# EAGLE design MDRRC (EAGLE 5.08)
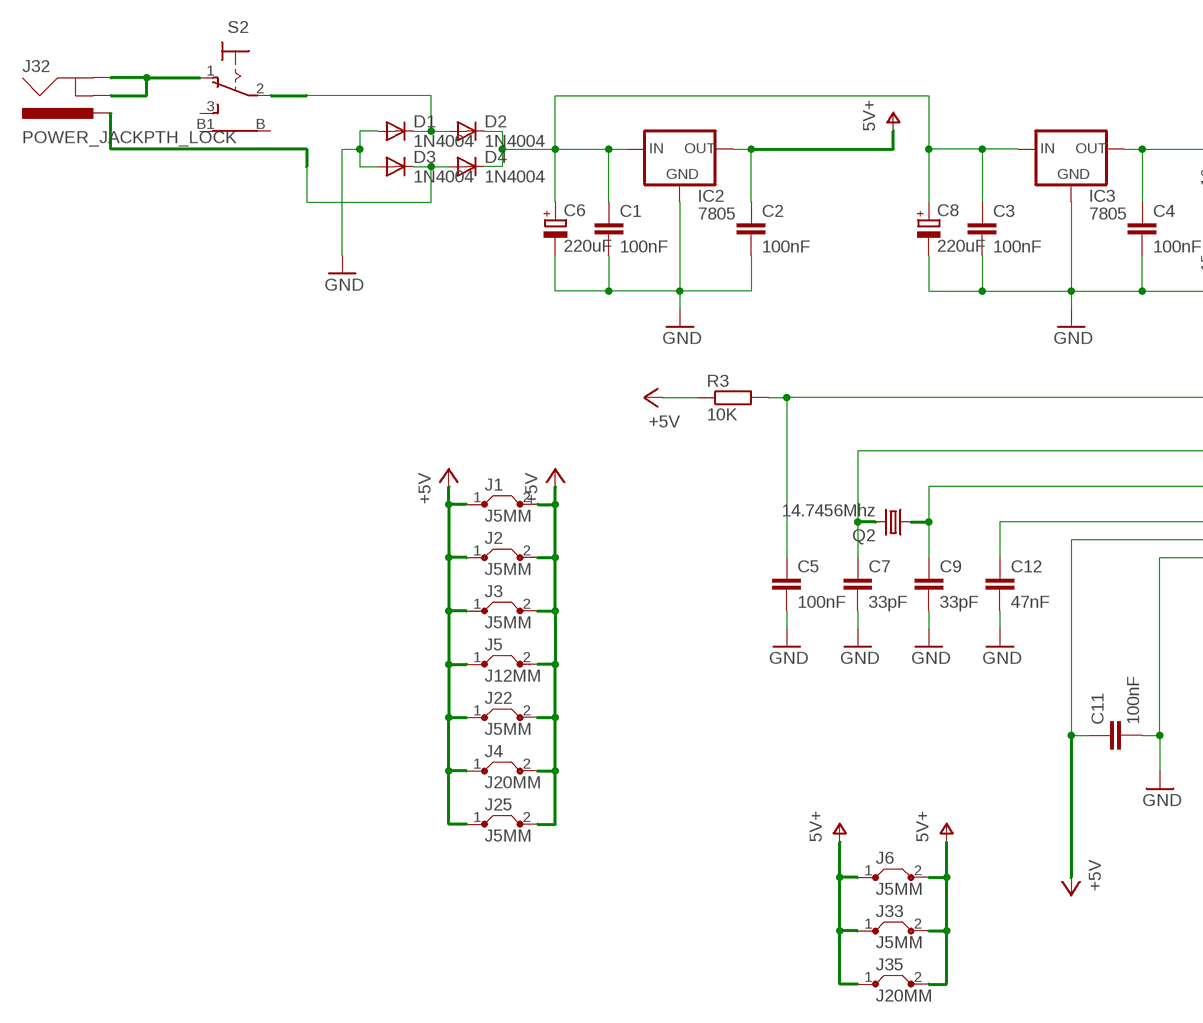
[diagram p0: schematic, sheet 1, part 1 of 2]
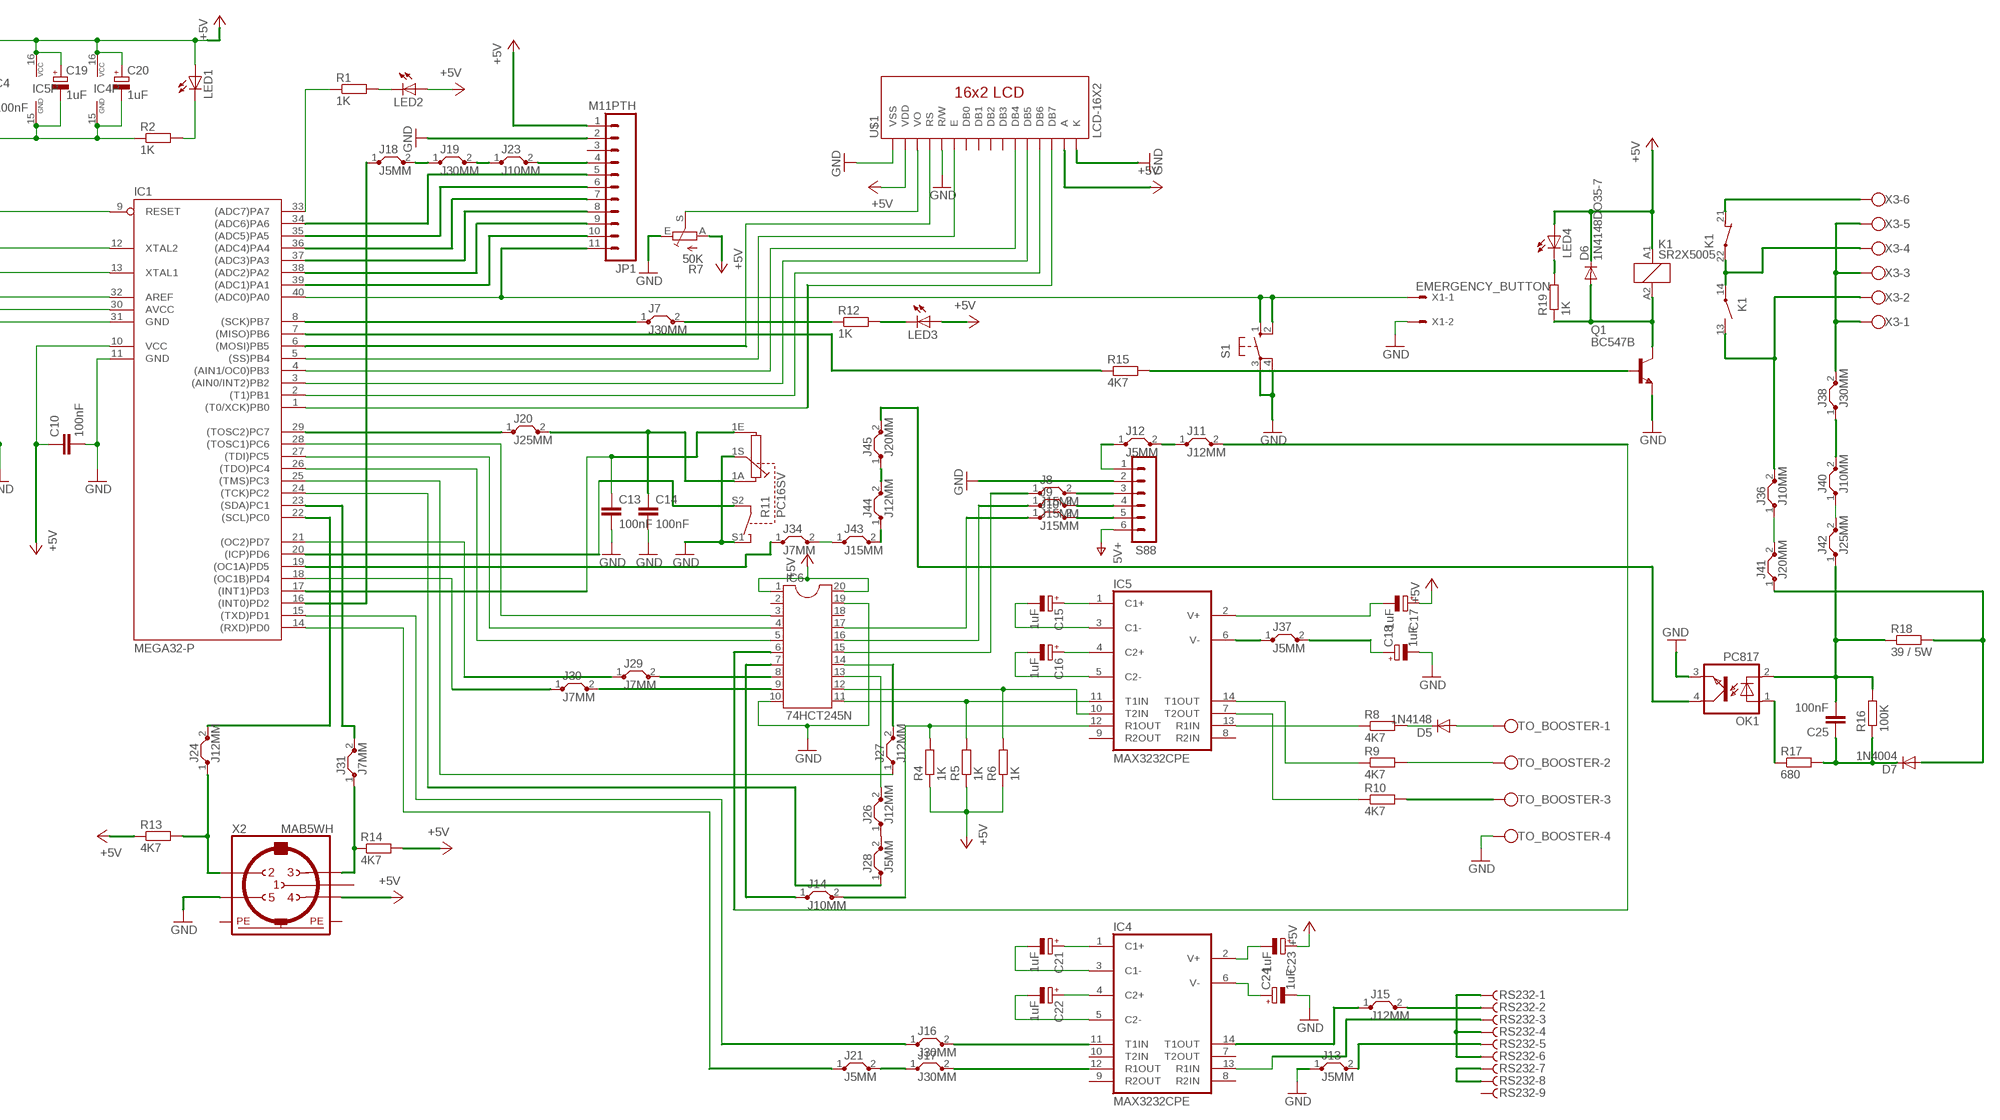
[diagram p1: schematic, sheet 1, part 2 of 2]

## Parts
C1  100nF  C-EU025-025X050  [C025-025X050]
C2  100nF  C-EU025-025X050  [C025-025X050]
C3  100nF  C-EU025-025X050  [C025-025X050]
C4  100nF  C-EU025-025X050  [C025-025X050]
C5  100nF  C-EU025-025X050  [C025-025X050]
C6  220uF  CPOL-EUE2.5-5  [E2,5-5]
C7  33pF  C-EU025-025X050  [C025-025X050]
C8  220uF  CPOL-EUE2.5-5  [E2,5-5]
C9  33pF  C-EU025-025X050  [C025-025X050]
C10  100nF  C-EU025-025X050  [C025-025X050]
C11  100nF  C-EU025-025X050  [C025-025X050]
C12  47nF  C-EU025-025X050  [C025-025X050]
C13  100nF  C-EU025-025X050  [C025-025X050]
C14  100nF  C-EU025-025X050  [C025-025X050]
C15  1uF  CPOL-EUE1.8-4  [E1,8-4]
C16  1uF  CPOL-EUE1.8-4  [E1,8-4]
C17  1uF  CPOL-EUE1.8-4  [E1,8-4]
C18  1uF  CPOL-EUE1.8-4  [E1,8-4]
C19  1uF  CPOL-EUE1.8-4  [E1,8-4]
C20  1uF  CPOL-EUE1.8-4  [E1,8-4]
C21  1uF  CPOL-EUE1.8-4  [E1,8-4]
C22  1uF  CPOL-EUE1.8-4  [E1,8-4]
C23  1uF  CPOL-EUE1.8-4  [E1,8-4]
C24  1uF  CPOL-EUE1.8-4  [E1,8-4]
C25  100nF  C-EU025-025X050  [C025-025X050]
D1  1N4004  [DO41-10]
D2  1N4004  [DO41-10]
D3  1N4004  [DO41-10]
D4  1N4004  [DO41-10]
D5  1N4148  1N4148DO35-10  [DO35-10]
D6  1N4148DO35-7  [DO35-7]
D7  1N4004  [DO41-10]
IC1  MEGA32-P  [DIL40]
IC2  7805  78XXS  [78XXS]
IC3  7805  78XXS  [78XXS]
IC4  MAX3232CPE  [DIL16]
IC5  MAX3232CPE  [DIL16]
IC6  74HCT245N  DIL20  [DIL20]
J1  J5MM  [05]
J2  J5MM  [05]
J3  J5MM  [05]
J4  J20MM  [20]
J5  J12MM  [12]
J6  J5MM  [05]
J7  J30MM  [30]
J8  J15MM  [15]
J9  J15MM  [15]
J10  J15MM  [15]
J11  J12MM  [12]
J12  J5MM  [05]
J13  J5MM  [05]
J14  J10MM  [10]
J15  J12MM  [12]
J16  J30MM  [30]
J17  J30MM  [30]
J18  J5MM  [05]
J19  J30MM  [30]
J20  J25MM  [25]
J21  J5MM  [05]
J22  J5MM  [05]
J23  J10MM  [10]
J24  J12MM  [12]
J25  J5MM  [05]
J26  J12MM  [12]
J27  J12MM  [12]
J28  J5MM  [05]
J29  J7MM  [07]
J30  J7MM  [07]
J31  J7MM  [07]
J32  POWER_JACKPTH_LOCK  [POWER_JACK_PTH_LOCK]
J33  J5MM  [05]
J34  J7MM  [07]
J35  J20MM  [20]
J36  J10MM  [10]
J37  J5MM  [05]
J38  J30MM  [30]
J40  J10MM  [10]
J41  J20MM  [20]
J42  J25MM  [25]
J43  J15MM  [15]
J44  J12MM  [12]
J45  J20MM  [20]
JP1  M11PTH  [1X11]
K1  SR2X5005  [SR2X]
LED1  LED3MM  [LED3MM]
LED2  LED3MM  [LED3MM]
LED3  LED3MM  [LED3MM]
LED4  LED3MM  [LED3MM]
OK1  PC817  [DIL04]
Q1  BC547B  [TO92]
Q2  14.7456Mhz  CRYSTALHC18U-H  [HC18U-H]
R1  1K  R-EU_0207/10  [0207/10]
R2  1K  R-EU_0207/10  [0207/10]
R3  10K  R-EU_0207/10  [0207/10]
R4  1K  R-EU_0207/10  [0207/10]
R5  1K  R-EU_0207/10  [0207/10]
R6  1K  R-EU_0207/10  [0207/10]
R7  50K  TRIM_EU-CA6V  [CA6V]
R8  4K7  R-EU_0207/10  [0207/10]
R9  4K7  R-EU_0207/10  [0207/10]
R10  4K7  R-EU_0207/10  [0207/10]
R11  PC16SV  [PC16SV]
R12  1K  R-EU_0207/10  [0207/10]
R13  4K7  R-EU_0207/10  [0207/10]
R14  4K7  R-EU_0207/10  [0207/10]
R15  4K7  R-EU_0207/10  [0207/10]
R16  100K  R-EU_0207/10  [0207/10]
R17  680  R-EU_0207/10  [0207/10]
R18  39 / 5W  R-EU_V235/17  [V235/17]
R19  1K  R-EU_0207/10  [0207/10]
RS232  F09HPS  [F09HP]
S1  10-XX  [B3F-10XX]
S2  LPV-1  [LPV-1]
S88  MA06-1  [MA06-1]
TO_BOOSTER  W237-04P  [W237-4P]
U$1  LCD-16X2  [LCD-16X2]
X1  EMERGENCY_BUTTON  22-23-2021  [22-23-2021]
X2  MAB5WH  [MAB5WH]
X3  W237-06P  [W237-6P]

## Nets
+5V: C4.1 C10.1 C11.1 C17.+ C19.+ C20.+ C23.+ D6.C IC1.10(VCC) IC1.30(AVCC) IC3.OUT IC4.16(VCC) IC5.16(VCC) IC6.1 IC6.20 J1.1 J1.2 J2.1 J2.2 J3.1 J3.2 J4.1 J4.2 J5.1 J5.2 J22.1 J22.2 J25.1 J25.2 JP1.1 K1.A1 LED1.A LED2.A LED3.A LED4.A R3.1 R4.1 R5.1 R6.1 R7.A R13.1 R14.2 U$1.2(VDD) U$1.15(A) X2.4
GND: C1.2 C2.2 C3.2 C4.2 C5.2 C6.- C7.2 C8.- C9.2 C10.2 C11.2 C12.2 C13.2 C14.2 C18.- C19.- C20.- C24.- D1.A D3.A IC1.11(GND) IC1.31(GND) IC2.GND IC3.GND IC4.15(GND) IC5.15(GND) IC6.10 IC6.19 J13.1 JP1.2 OK1.3(EMIT) Q1.1(E) R2.1 R7.E R11.1S R11.S1 S1.3(P) S1.4(P1) S88.2 TO_BOOSTER.4 U$1.1(VSS) U$1.5(R/W) U$1.16(K) X1.2 X2.5
N$1: D1.C D2.A S2.2(P)
N$2: D3.C D4.A J32.PWR
N$3: C7.1 IC1.12(XTAL2) Q2.2
N$4: C1.1 C3.1 C6.+ C8.+ D2.C D4.C IC2.IN IC3.IN
N$5: C9.1 IC1.13(XTAL1) Q2.1
N$6: C12.1 IC1.32(AREF)
N$7: LED1.K(C) R2.2
N$8: C5.1 IC1.9(RESET) R3.2
N$9: IC1.33((ADC7)PA7) R1.1
N$10: LED2.K(C) R1.2
N$11: IC1.40((ADC0)PA0) JP1.11 S1.1(S) S1.2(S1) X1.1
N$12: IC1.8((SCK)PB7) J7.1
N$13: LED3.K(C) R12.2
N$14: IC6.7 J14.1
N$15: IC1.28((TOSC1)PC6) IC6.3
N$16: IC1.27((TDI)PC5) IC6.4
N$17: IC1.26((TDO)PC4) IC6.5
N$18: IC1.21((OC2)PD7) J29.1
N$19: IC1.18((OC1B)PD4) J30.1
N$20: IC1.25((TMS)PC3) J27.1
N$21: IC1.24((TCK)PC2) J28.1
N$22: C14.1 J20.2 R11.1A
N$23: IC5.11(T1IN) IC6.11 R5.2
N$24: IC5.10(T2IN) IC6.12 R6.2
N$25: IC5.12(R1OUT) J14.2 R4.2
N$26: J7.2 R12.1
N$27: C16.- IC5.5(C2-)
N$28: C15.- IC5.3(C1-)
N$29: C15.+ IC5.1(C1+)
N$30: C16.+ IC5.4(C2+)
N$31: C17.- IC5.2(V+)
N$32: C18.+ J37.2
N$33: IC6.6 J11.2
N$34: IC6.15 J8.1
N$35: IC6.16 J9.1
N$36: IC6.17 J10.1
N$37: C21.+ IC4.1(C1+)
N$38: C21.- IC4.3(C1-)
N$39: C22.+ IC4.4(C2+)
N$40: C22.- IC4.5(C2-)
N$41: C23.- IC4.2(V+)
N$42: C24.+ IC4.6(V-)
N$43: IC1.15((TXD)PD1) J16.1
N$44: IC1.14((RXD)PD0) J21.1
N$45: IC4.14(T1OUT) J15.1
N$46: IC4.13(R1IN) RS232.3
N$47: IC1.1((T0/XCK)PB0) U$1.14(DB7)
N$48: IC1.2((T1)PB1) U$1.13(DB6)
N$49: IC1.3((AIN0/INT2)PB2) U$1.12(DB5)
N$50: IC1.4((AIN1/OC0)PB3) U$1.11(DB4)
N$51: IC1.5((SS)PB4) U$1.6(E)
N$52: IC1.6((MOSI)PB5) U$1.4(RS)
N$53: R7.S U$1.3(VO)
N$54: IC5.14(T1OUT) R9.1
N$55: IC5.7(T2OUT) R10.1
N$56: IC5.13(R1IN) R8.1
N$57: R10.2 TO_BOOSTER.3
N$58: R9.2 TO_BOOSTER.2
N$59: D5.C R8.2
N$60: D5.A TO_BOOSTER.1
N$61: J8.2 S88.3
N$62: J9.2 S88.4
N$63: J10.2 S88.5
N$64: J12.1 S88.1
N$65: J11.1 J12.2
N$66: J13.2 RS232.5
N$67: IC1.7((MISO)PB6) R15.1
N$68: RS232.1 RS232.4 RS232.6
N$69: RS232.7 RS232.8
N$70: J15.2 RS232.2
N$71: IC4.11(T1IN) J16.2
N$72: IC1.39((ADC1)PA1) JP1.10
N$73: IC1.38((ADC2)PA2) JP1.9
N$74: IC4.12(R1OUT) J17.2
N$75: IC1.37((ADC3)PA3) JP1.8
N$76: J17.1 J21.2
N$77: IC6.13 J26.2
N$78: IC6.14 J27.2
N$79: J26.1 J28.2
N$80: IC6.8 J29.2
N$81: IC6.9 J30.2
N$82: IC1.22((SCL)PC0) J24.2
N$83: J32.GND J32.GNDBREAK S2.1(O)
N$84: IC1.20((ICP)PD6) R11.S2
N$85: C13.1 IC1.17((INT1)PD3) R11.1E
N$86: IC1.29((TOSC2)PC7) J20.1
N$87: IC1.36((ADC4)PA4) JP1.7
N$88: IC1.19((OC1A)PD5) J34.1
N$89: J36.1 J41.2
N$90: J34.2 J43.1
N$91: IC1.35((ADC5)PA5) JP1.6
N$92: IC1.34((ADC6)PA6) JP1.5
N$93: IC1.16((INT0)PD2) J18.1
N$94: J18.2 J19.1
N$95: J19.2 J23.1
N$96: J23.2 JP1.4
N$97: IC1.23((SDA)PC1) J31.2
N$98: J31.1 R14.1 X2.3
N$99: J24.1 R13.2 X2.2
N$100: IC5.6(V-) J37.1
N$101: Q1.2(B) R15.2
N$102: D6.A K1.A2 Q1.3(C) R19.1
N$103: J36.2 K1.13(3:S) X3.2
N$104: J38.1 J40.2
N$105: K1.14(3:P) K1.22(2:P) X3.4
N$106: J38.2 X3.1 X3.3 X3.5
N$108: K1.21(2:O) X3.6
N$109: J40.1 J42.2
N$110: J43.2 J44.1
N$111: J44.2 J45.1
N$112: J45.2 OK1.4(COL)
N$113: C25.2 J42.1 OK1.2(C) R16.2 R18.1
N$114: OK1.1(A) R17.1
N$115: C25.1 D7.C R16.1 R17.2
N$116: D7.A J41.1 R18.2
N$117: LED4.K(C) R19.2
V+: C2.1 IC2.OUT J6.1 J6.2 J33.1 J33.2 J35.1 J35.2 S88.6 ; supply symbol labelled 5V+
Unconnected: IC4.7(T2OUT) IC4.8(R2IN) IC4.9(R2OUT) IC4.10(T2IN) IC5.8(R2IN) IC5.9(R2OUT) IC6.2 IC6.18 JP1.3 RS232.9 S2.3(S) S2.B S2.B1 U$1.7(DB0) U$1.8(DB1) U$1.9(DB2) U$1.10(DB3) X2.1

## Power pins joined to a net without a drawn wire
PE: X2.PE X2.PE@(PE)

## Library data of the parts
C1-C5 C7 C9-C14 C25 = rcl:C-EU: CAPACITOR, European symbol
C6 C8 C15-C24 = rcl:CPOL-EU: POLARIZED CAPACITOR, European symbol
D1-D4 D7 = diode:1N4004: DIODE
D5 D6 = diode:1N4148: DIODE
IC1 = atmel:MEGA32-P: MICROCONTROLLER 32 Kbytes FLASH 2 Kbytes SRAM 1 Kbytes EEPROM USART 8-channel 10 bit ADC Source: www.atmel.com .. doc2503.pdf
IC2 IC3 = v-reg:78XXS: VOLTAGE REGULATOR
IC4 IC5 = maxim:MAX3232*: True RS-232 Transceivers 3.0V to 5.5V, Low-Power up to 1Mbps, Using Four 0.1µF External Capacitors Source: http://pdfserv.maxim-ic.com/en/ds/MAX3222-MAX3241.pdf
IC6 = ic-package:DIL20: Dual In Line / Socket
J1-J31 J33-J38 J40-J45 = jumper:J: Bridge
J32 = SparkFun:POWER_JACK: Power Jack This is the standard 5.5mm barrel jack for power. The PTH is the most common, proven, reliable, footprint. All others are experimental. The Slot footprint only works if the mill layer is transmitted to the PCB fab house so be warned. Spark Fun Electronics SKU : PRT-00119. Mating wall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
JP1 = SparkFun:M11: Header 11 Standard 11-pin 0.1" header. Use with straight break away headers (SKU : PRT-00116), right angle break away headers (PRT-00553), swiss pins (PRT-00743), machine pins (PRT-00117), and female headers (PRT-00115).
K1 = relay:SR2X5*: Safety Relay 2 pole 6 A SCHRACK Source: http://www.schrack.com/.. 5809.pdf
LED1-LED4 = led:LED: LED
OK1 = optocoupler:PC817: SHARP OPTO COUPLER
Q1 = transistor-npn:BC547*: NPN Transistor
Q2 = crystal:CRYSTAL: CRYSTAL
R1-R6 R8-R10 R12-R14 R16 R17 R19 = rcl:R-EU_: RESISTOR, European symbol
R7 = pot:TRIM_EU-: POTENTIOMETER
R11 = rotary_voti:PC16SV: POTENTIOMETER vertical single carbon potentiometer with switch, 16 mm
R15 R18 = resistor:R-EU_: RESISTOR, European symbol
RS232 = con-subd:F09?S: SUB-D
S1 = switch-omron:10-XX: OMRON SWITCH
S2 = switch:LPV-1: TOGGLE SWITCH
S88 = con-lstb:MA06-1: PIN HEADER
TO_BOOSTER = con-wago-508:W237-04P: WAGO SREW CLAMP
U$1 = SparkFun:LCD-16X2
X1 = con-molex:22-23-2021: .100" (2.54mm) Center Header - 2 Pin
X2 = con_midi:MAB5WH: Female CONNECTOR 5 pins with shield, horizontal (DIN 45327)
X3 = con-wago-508:W237-06P: WAGO SREW CLAMP

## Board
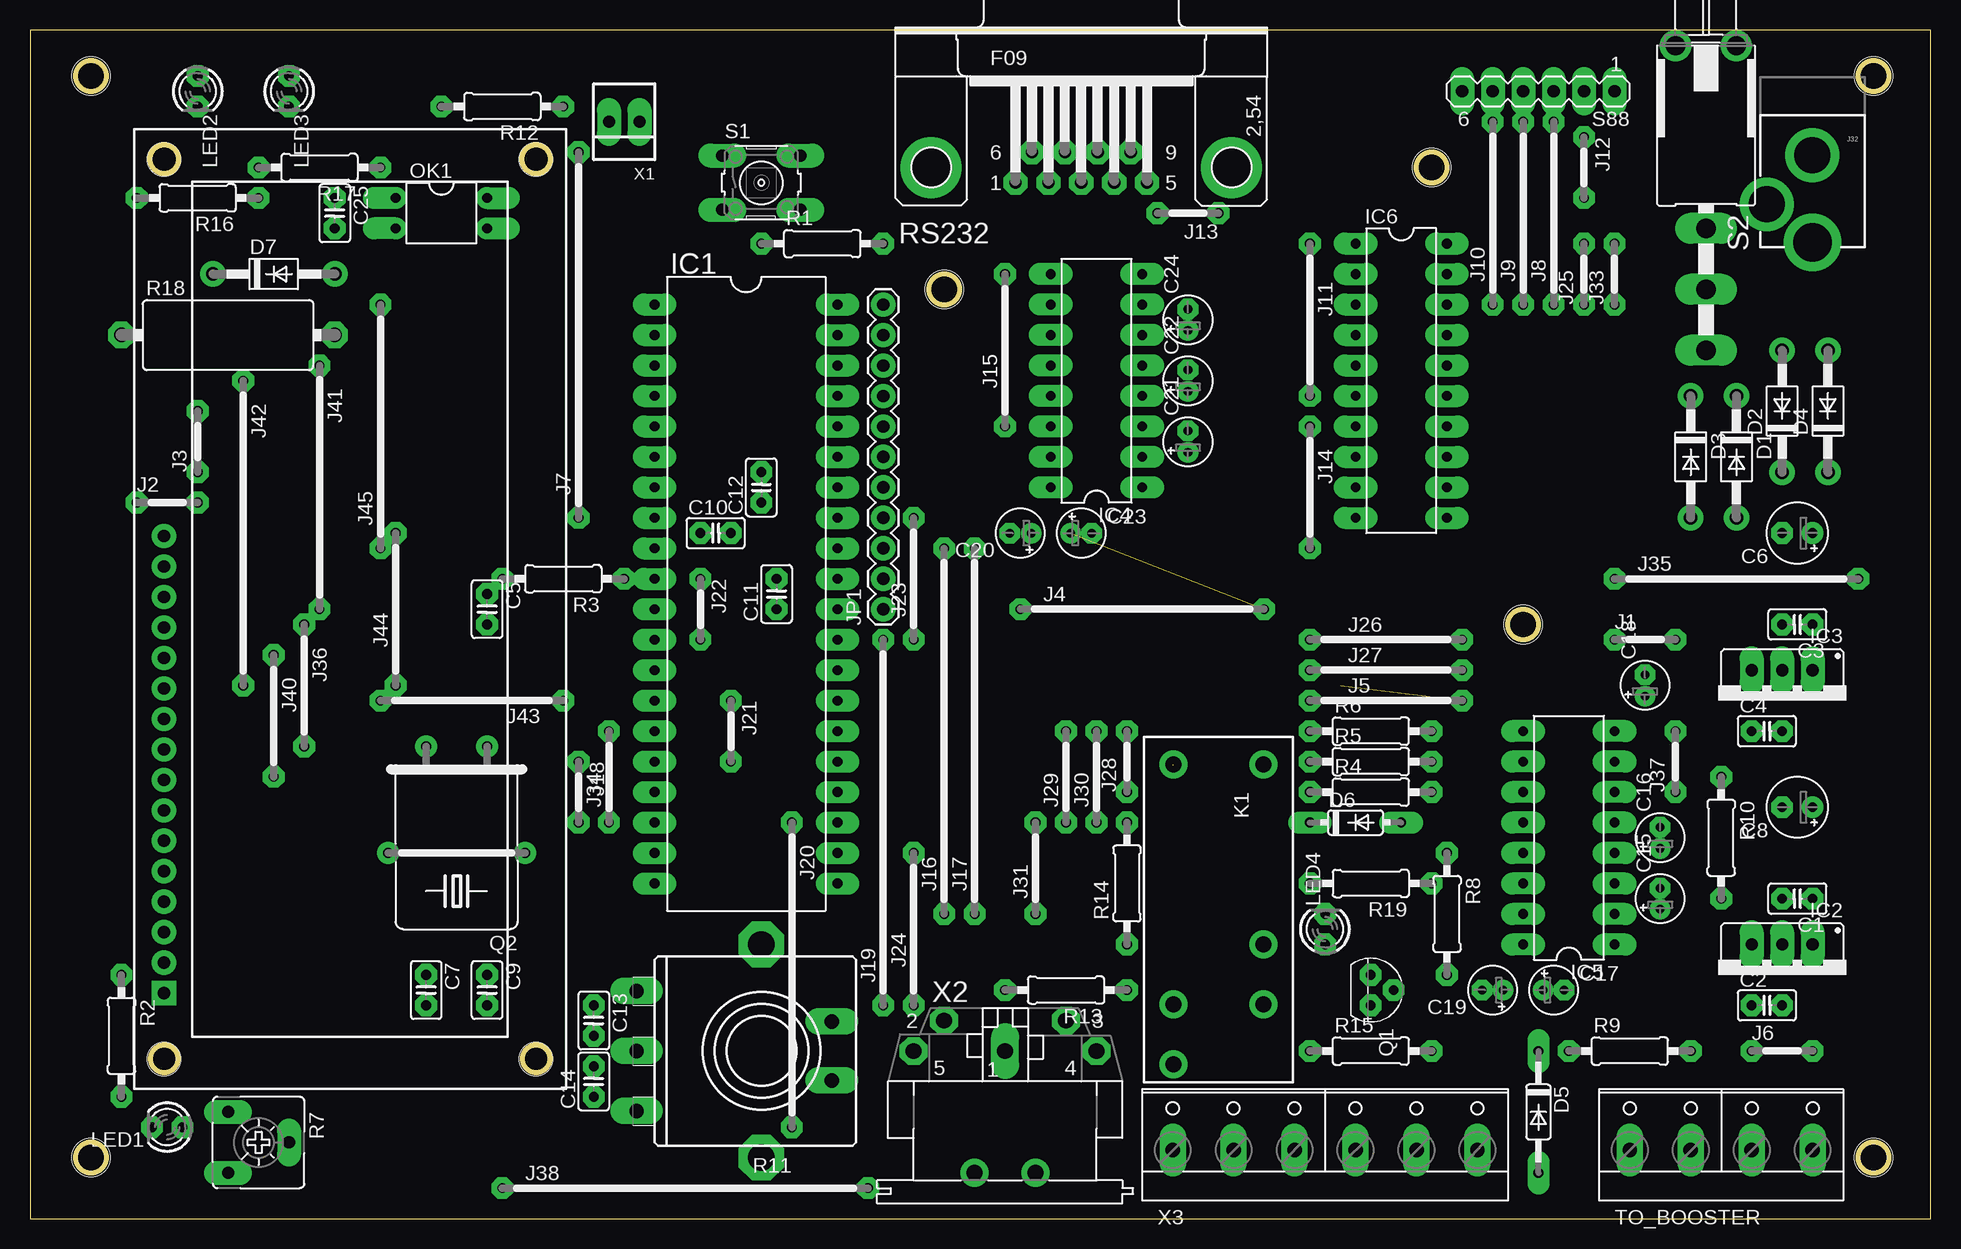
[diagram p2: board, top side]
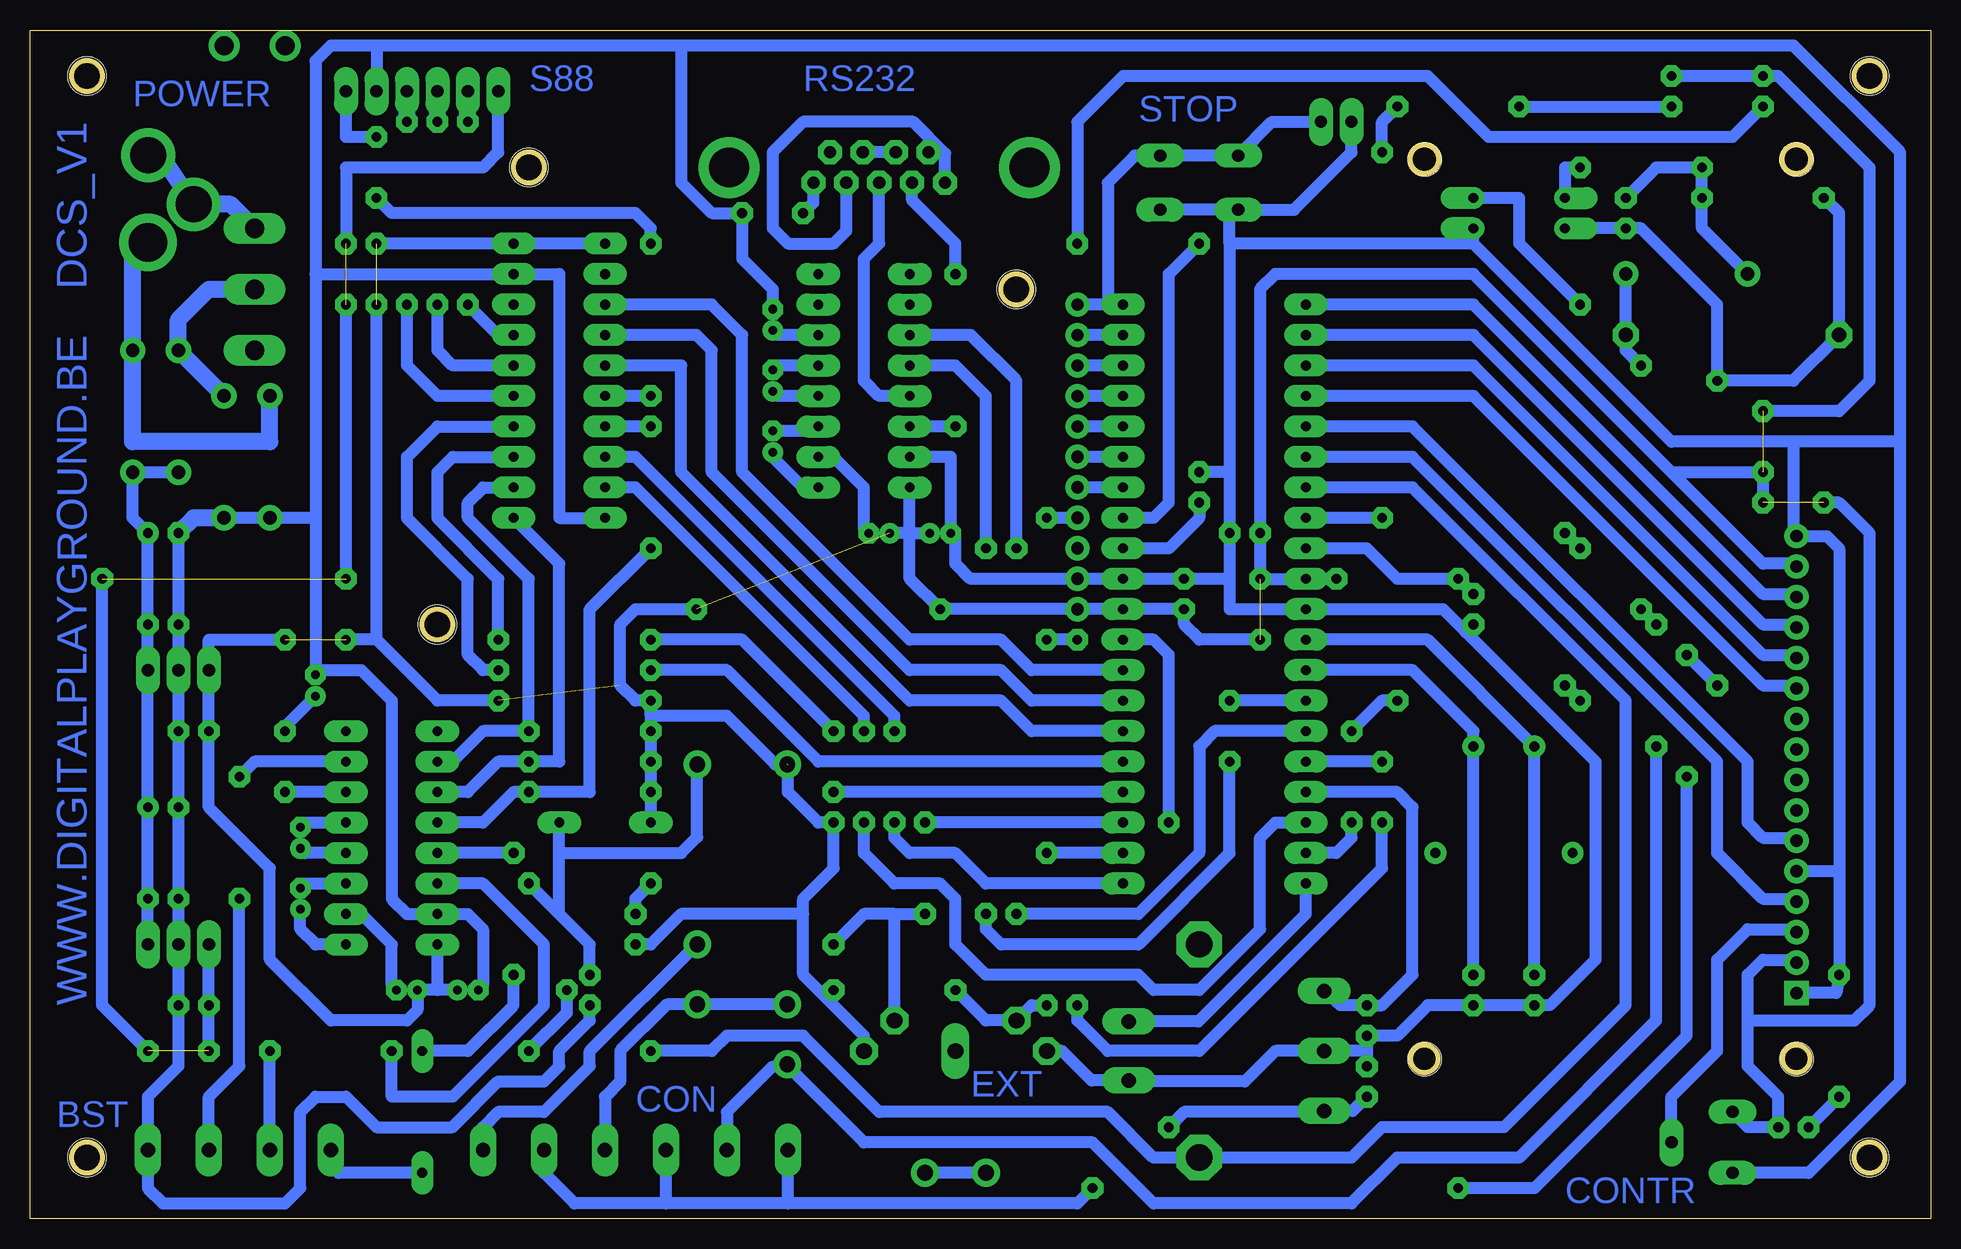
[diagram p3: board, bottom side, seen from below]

Size 158.42 x 99.05 mm. Coordinates in mm from the lower left corner, seen from the top.
Outline: 0,0 158.42,0 158.42,99.05 0,99.05 0,0
Outline: circle at 5.08,95.25 radius 1.27
Outline: circle at 5.08,5.08 radius 1.27
Outline: circle at 153.67,5.08 radius 1.27
Outline: circle at 153.67,95.25 radius 1.27
Outline: circle at 116.84,87.63 radius 1.27
Outline: circle at 76.2,77.47 radius 1.27
Outline: circle at 124.46,49.53 radius 1.27
Outline: circle at 42.2,13.33 radius 1.13
Outline: circle at 11.2,13.33 radius 1.13
Outline: circle at 11.2,88.33 radius 1.17
Outline: circle at 42.2,88.33 radius 1.17
Copper layers (1*16): Top 0.8mm / dielectric 1.3mm / Bottom 0.8mm
Design rules "DRC settings smallest": minimum track width 0.8mm, minimum drill 24mil, track to track 0.2mm, track to pad 0.2mm, pad to pad 0.2mm, via to via 0.2mm, smd to smd 8mil, copper to edge 0.3mm, drill to drill 0.3mm, minimum pad ring 0.5mm, minimum via ring 1mm, stop-mask expansion 4mil, vias tented up to drill 0mil, thermal gap 10mil
Holes 3.2 mm at 5.08,95.25 5.08,5.08 153.67,95.25 76.2,77.47 116.84,87.63 124.46,49.53 153.67,5.08

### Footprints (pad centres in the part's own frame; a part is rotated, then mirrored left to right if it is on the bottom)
C025-025X050 = drill 0.813 octagon: 1 -1.27,0; 2 1.27,0
E2,5-5 = drill 0.813 pad 1.6 round: + -1.27,0 | drill 0.813 pad 1.6 octagon: - 1.27,0
E1,8-4 = drill 0.711 pad 1.168 round: + -0.889,0 | drill 0.711 pad 1.168 octagon: - 0.889,0
DO41-10 = drill 1.118 round: A 5.08,0; C -5.08,0
DO35-10 = drill 0.813 long: A 5.08,0; C -5.08,0
DO35-7 = drill 0.813 long: A 3.81,0; C -3.81,0
DIL40 = drill 0.813 long: 1 -24.13,-7.62; 2 -21.59,-7.62; 3 -19.05,-7.62; 4 -16.51,-7.62; 5 -13.97,-7.62; 6 -11.43,-7.62; 7 -8.89,-7.62; 8 -6.35,-7.62; 9 -3.81,-7.62; 10 -1.27,-7.62; 11 1.27,-7.62; 12 3.81,-7.62; 13 6.35,-7.62; 14 8.89,-7.62; 15 11.43,-7.62; 16 13.97,-7.62; 17 16.51,-7.62; 18 19.05,-7.62; 19 21.59,-7.62; 20 24.13,-7.62; 21 24.13,7.62; 22 21.59,7.62; 23 19.05,7.62; 24 16.51,7.62; 25 13.97,7.62; 26 11.43,7.62; 27 8.89,7.62; 28 6.35,7.62; 29 3.81,7.62; 30 1.27,7.62; 31 -1.27,7.62; 32 -3.81,7.62; 33 -6.35,7.62; 34 -8.89,7.62; 35 -11.43,7.62; 36 -13.97,7.62; 37 -16.51,7.62; 38 -19.05,7.62; 39 -21.59,7.62; 40 -24.13,7.62
78XXS = drill 1.016 long: GND 0,-2.54; IN -2.54,-2.54; OUT 2.54,-2.54
DIL16 = drill 0.813 long: 1 -8.89,-3.81; 2 -6.35,-3.81; 3 -3.81,-3.81; 4 -1.27,-3.81; 5 1.27,-3.81; 6 3.81,-3.81; 7 6.35,-3.81; 8 8.89,-3.81; 9 8.89,3.81; 10 6.35,3.81; 11 3.81,3.81; 12 1.27,3.81; 13 -1.27,3.81; 14 -3.81,3.81; 15 -6.35,3.81; 16 -8.89,3.81
DIL20 = drill 0.813 long: 1 -11.43,-3.81; 2 -8.89,-3.81; 3 -6.35,-3.81; 4 -3.81,-3.81; 5 -1.27,-3.81; 6 1.27,-3.81; 7 3.81,-3.81; 8 6.35,-3.81; 9 8.89,-3.81; 10 11.43,-3.81; 11 11.43,3.81; 12 8.89,3.81; 13 6.35,3.81; 14 3.81,3.81; 15 1.27,3.81; 16 -1.27,3.81; 17 -3.81,3.81; 18 -6.35,3.81; 19 -8.89,3.81; 20 -11.43,3.81
05 = drill 0.813 pad 1.6 octagon: 1 -2.54,0; 2 2.54,0
20 = drill 0.813 pad 1.6 octagon: 1 -10.16,0; 2 10.16,0
12 = drill 0.813 pad 1.6 octagon: 1 -6.35,0; 2 6.35,0
30 = drill 0.813 pad 1.6 octagon: 1 -15.24,0; 2 15.24,0
15 = drill 0.813 pad 1.6 octagon: 1 -7.62,0; 2 7.62,0
10 = drill 0.813 pad 1.6 octagon: 1 -5.08,0; 2 5.08,0
25 = drill 0.813 pad 1.6 octagon: 1 -12.7,0; 2 12.7,0
07 = drill 0.813 pad 1.6 octagon: 1 -3.81,0; 2 3.81,0
POWER_JACK_PTH_LOCK = drill 2.997 round: GND 0.025,6.608; GNDBREAK 3.812,10.7 | drill 3.2 round: PWR 0,13.878
1X11 = drill 1.016 pad 1.88 round: 1 0,0; 2 2.54,0; 3 5.08,0; 4 7.62,0; 5 10.16,0; 6 12.7,0; 7 15.24,0; 8 17.78,0; 9 20.32,0; 10 22.86,0; 11 25.4,0
SR2X = drill 1.3 round: 13 12.54,-3.75; 14 7.54,-3.75; 21 2.54,3.75; 22 7.54,3.75; A1 -12.46,-3.75; A2 -12.46,3.75
LED3MM = drill 0.813 octagon: A -1.27,0; K 1.27,0
DIL04 = drill 0.813 offset: 1 -1.27,-3.81; 2 1.27,-3.81; 3 1.27,3.81; 4 -1.27,3.81
TO92 = drill 0.813 octagon: 1 1.27,0; 2 0,1.905; 3 -1.27,0
HC18U-H = drill 0.813 round: 1 -2.54,-5.08; 2 2.54,-5.08; M -5.715,3.81; M1 5.715,3.81
0207/10 = drill 0.813 octagon: 1 -5.08,0; 2 5.08,0
CA6V = drill 1.016 long: A -2.54,-2.54; E 2.54,-2.54; S 0,2.54
PC16SV = drill 1.2 long: 1A -5,10.4; 1E 5,10.4; 1S 0,10.4; S1 -2.46,-5.87; S2 2.46,-5.87 | drill 2.2 pad 3.81 octagon: P$1 -8.89,0; P$2 8.89,0
V235/17 = drill 1.194 octagon: 1 -8.89,0; 2 8.89,0
F09HP = drill 1.016 octagon: 1 -5.486,-1.27; 2 -2.743,-1.27; 3 0,-1.27; 4 2.743,-1.27; 5 5.486,-1.27; 6 -4.115,1.27; 7 -1.372,1.27; 8 1.372,1.27; 9 4.115,1.27 | drill 3.302 pad 5.08 round: G1 -12.522,0; G2 12.522,0
B3F-10XX = drill 1.016 long: 1 -3.251,2.261; 2 3.251,2.261; 3 -3.251,-2.261; 4 3.251,-2.261
LPV-1 = drill 1.6 long: 1 0,15.24; 2 0,20.32; 3 0,25.4 | drill 1.6 pad 2.54 round: B -2.54,0; B1 2.54,0
MA06-1 = drill 1.016 long: 1 -6.35,0; 2 -3.81,0; 3 -1.27,0; 4 1.27,0; 5 3.81,0; 6 6.35,0
W237-4P = drill 1.194 long: 1 -7.62,-0.635; 2 -2.54,-0.635; 3 2.54,-0.635; 4 7.62,-0.635
LCD-16X2 = drill 1.016 square: 1 -32,15.5 | drill 1.016 round: 2 -29.46,15.5; 3 -26.92,15.5; 4 -24.38,15.5; 5 -21.84,15.5; 6 -19.3,15.5; 7 -16.76,15.5; 8 -14.22,15.5; 9 -11.68,15.5; 10 -9.14,15.5; 11 -6.6,15.5; 12 -4.06,15.5; 13 -1.52,15.5; 14 1.02,15.5; 15 3.56,15.5; 16 6.1,15.5 | hole 2.8: -37.5,15.5; -37.5,-15.5; 37.5,15.5; 37.5,-15.5
22-23-2021 = drill 1 long: 1 -1.27,0; 2 1.27,0
MAB5WH = drill 1.321 long: 1 0,5.08 | drill 1.321 octagon: 2 -5.08,7.62; 3 5.08,7.62; 4 7.62,5.08; 5 -7.62,5.08 | drill 1.321 round: PE -2.54,-5.08; PE@ 2.54,-5.08
W237-6P = drill 1.194 long: 1 -12.7,-0.635; 2 -7.62,-0.635; 3 -2.54,-0.635; 4 2.54,-0.635; 5 7.62,-0.635; 6 12.7,-0.635

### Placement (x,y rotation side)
C1  147.32,26.67 180 top
C2  144.78,17.78 0 top
C3  147.32,49.53 180 top
C4  144.78,40.64 0 top
C5  38.1,50.8 270 top
C6  147.32,57.15 180 top
C7  33.02,19.05 270 top
C8  147.32,34.29 180 top
C9  38.1,19.05 270 top
C10  57.15,57.15 0 top
C11  62.23,52.07 90 top
C12  60.96,60.96 90 top
C13  46.99,16.51 270 top
C14  46.99,11.43 90 top
C15  135.89,26.67 90 top
C16  135.89,31.75 90 top
C17  127,19.05 0 top
C18  134.62,44.45 90 top
C19  121.92,19.05 180 top
C20  82.55,57.15 180 top
C21  96.52,64.77 90 top
C22  96.52,69.85 90 top
C23  87.63,57.15 0 top
C24  96.52,74.93 90 top
C25  25.4,83.82 270 top
D1  142.24,63.5 270 top
D2  146.05,67.31 90 top
D3  138.43,63.5 270 top
D4  149.86,67.31 90 top
D5  125.73,8.89 270 top
D6  110.49,33.02 0 top
D7  20.32,78.74 0 top
IC1  59.69,52.07 270 top
IC2  146.05,20.32 180 top
IC3  146.05,43.18 180 top
IC4  88.9,69.85 90 top
IC5  128.27,31.75 90 top
IC6  114.3,69.85 270 top
J1  134.62,48.26 0 top
J2  11.43,59.69 0 top
J3  13.97,64.77 90 top
J4  92.71,50.8 0 top
J5  113.03,43.18 0 top
J6  146.05,13.97 0 top
J7  45.72,73.66 90 top
J8  127,83.82 90 top
J9  124.46,83.82 90 top
J10  121.92,83.82 90 top
J11  106.68,74.93 270 top
J12  129.54,87.63 270 top
J13  96.52,83.82 180 top
J14  106.68,60.96 270 top
J15  81.28,72.39 90 top
J16  76.2,40.64 90 top
J17  78.74,40.64 90 top
J18  45.72,35.56 270 top
J19  71.12,33.02 90 top
J20  63.5,20.32 270 top
J21  58.42,40.64 270 top
J22  55.88,50.8 270 top
J23  73.66,53.34 90 top
J24  73.66,24.13 90 top
J25  129.54,78.74 90 top
J26  113.03,48.26 0 top
J27  113.03,45.72 0 top
J28  91.44,38.1 90 top
J29  86.36,36.83 90 top
J30  88.9,36.83 90 top
J31  83.82,29.21 90 top
J32  148.59,95.25 180 top
J33  132.08,78.74 90 top
J34  48.26,36.83 90 top
J35  142.24,53.34 0 top
J36  22.86,44.45 270 top
J37  137.16,38.1 90 top
J38  54.61,2.54 0 top
J40  20.32,41.91 270 top
J41  24.13,60.96 270 top
J42  17.78,57.15 270 top
J43  36.83,43.18 180 top
J44  30.48,50.8 90 top
J45  29.21,66.04 90 top
JP1  71.12,50.8 90 top
K1  99.06,25.4 270 top
LED1  11.43,7.62 180 top
LED2  13.97,93.98 270 top
LED3  21.59,93.98 270 top
LED4  107.95,24.13 90 top
OK1  34.29,83.82 270 top
Q1  111.76,19.05 270 top
Q2  35.56,34.29 180 top
R1  66.04,81.28 0 top
R2  7.62,15.24 270 top
R3  44.45,53.34 180 top
R4  111.76,35.56 0 top
R5  111.76,38.1 0 top
R6  111.76,40.64 0 top
R7  19.05,6.35 270 top
R8  118.11,25.4 270 top
R9  133.35,13.97 0 top
R10  140.97,31.75 270 top
R11  60.96,13.97 90 top
R12  39.37,92.71 180 top
R13  86.36,19.05 180 top
R14  91.44,27.94 90 top
R15  111.76,13.97 0 top
R16  13.97,85.09 180 top
R17  24.13,87.63 180 top
R18  16.51,73.66 0 top
R19  111.76,27.94 180 top
RS232  87.63,87.63 0 top
S1  60.96,86.36 0 top
S2  139.7,97.79 180 top
S88  125.73,93.98 180 top
TO_BOOSTER  140.97,6.35 0 top
U$1  26.67,50.8 90 top
X1  49.53,91.44 180 top
X2  81.28,8.89 0 top
X3  107.95,6.35 0 top

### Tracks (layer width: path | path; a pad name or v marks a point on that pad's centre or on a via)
+5V  (8 unrouted)
  Bottom 1.016: 21.59,62.23 13.97,54.61 11.42,54.61 U$1.15 | 21.59,62.23 38.1,78.74 54.61,78.74 55.88,77.47 C10.1 J22.1 IC1.10 R3.1 | 21.59,62.23 J3.1 J2.2 | J3.2 7.62,67.31 5.08,69.85 5.08,87.63 12.7,95.25 LED2.A LED3.A | IC6.1 IC6.20 J25.2 | J22.2 60.96,48.26 62.23,49.53 C11.1 IC1.30 JP1.1 J4.1 85.09,53.34 85.09,57.15 | J1.2 143.51,48.26 IC3.OUT C4.1 143.51,34.29 138.43,29.21 138.43,21.59 133.35,16.51 127,16.51 126.11,17.4 C17.+ 124.46,19.05 | 85.09,57.15 C23.+ | 85.09,57.15 C20.+ | 85.09,57.15 IC4.16 | 129.54,48.26 J25.1 | 129.54,48.26 124.46,43.18 J5.2 | C19.+ 124.46,19.05 | 124.46,19.05 IC5.16 | 93.98,25.4 93.98,20.32 92.08,18.41 | 93.98,25.4 93.98,26.67 91.44,29.21 R14.2 92.71,33.02 95.25,35.56 95.25,37.8 | 129.54,48.26 J1.1 | 106.68,41.91 R6.1 R5.1 R4.1 D6.C | 106.68,41.91 J5.1 107.95,43.18 109.22,44.45 109.22,49.53 107.95,50.8 J4.2 | R7.A 15.24,7.62 LED1.A 12.7,10.16 15.24,12.7 15.24,16.51 | 15.24,16.51 15.24,20.32 13.97,21.59 11.42,21.59 U$1.2 | J2.1 7.62,59.69 5.08,57.15 5.08,17.78 6.35,16.51 15.24,16.51 | LED4.A 106.68,22.86 104.14,25.4 93.98,25.4 | K1.A1 96.28,37.86 100.33,41.91 106.68,41.91 | 92.08,18.41 88.9,15.24 X2.4 | 92.08,18.41 R13.1
GND
  Bottom 1.016: D1.A D3.A 134.62,58.42 | C6.- C3.2 IC3.GND C4.2 C8.- C1.2 IC2.GND C2.2 146.05,12.7 148.59,10.16 TO_BOOSTER.4 148.59,2.54 147.32,1.27 137.16,1.27 135.89,2.54 135.89,8.89 134.62,10.16 132.08,10.16 129.54,7.62 123.19,7.62 119.38,11.43 115.57,11.43 114.3,12.7 114.3,13.97 111.76,16.51 Q1.1 | 38.1,81.28 21.59,64.77 11.43,64.77 | R7.E 10.16,3.81 2.54,11.43 2.54,64.77 | 134.62,78.74 134.62,96.52 133.35,97.79 129.54,97.79 | 104.14,97.79 11.43,97.79 2.54,88.9 2.54,64.77 | 104.14,97.79 129.54,97.79 | 2.54,64.77 11.43,64.77 | 58.42,81.28 58.42,62.23 | 58.42,62.23 C10.2 58.42,53.34 | 58.42,62.23 C12.2 | 104.14,97.79 104.14,86.36 101.6,83.82 J13.1 99.06,80.01 96.52,77.47 C24.- | IC6.10 114.3,58.42 114.3,78.74 IC6.19 134.62,78.74 | 58.42,53.34 58.42,50.8 IC1.11 40.64,50.8 38.73,48.9 | 58.42,53.34 C11.2 IC1.31 JP1.2 80.01,53.34 81.28,54.61 81.28,56.77 C20.- 81.66,63.5 IC4.15 | 134.62,78.74 134.62,58.42 | 134.62,58.42 C18.- 134.24,45.72 130.81,45.72 128.27,43.18 128.27,26.67 127,25.4 IC5.15 121.92,25.4 120.65,24.13 120.65,19.43 C19.- | 38.1,81.28 58.42,81.28 | 58.42,84.1 S1.3 53.06,84.1 48.26,88.9 X1.2 | 58.42,84.1 S1.4 | 46.99,13.97 C14.2 | 46.99,13.97 C13.2 44.45,15.24 41.91,17.78 C9.2 C7.2 31.75,17.78 27.94,21.59 27.94,38.1 38.73,48.9 | 38.1,81.28 OK1.3 | 129.54,97.79 S88.2 | X2.5 72.39,13.97 69.93,11.51 R11.S1 66.75,11.43 57.15,11.43 54.61,13.97 R11.1S 46.99,13.97 | 58.42,81.28 58.42,84.1 | 7.62,29.21 R2.1 7.87,18.8 U$1.1 | 7.62,29.21 7.62,55.88 8.64,56.9 U$1.16 11.43,57.15 11.43,64.77 | U$1.5 7.87,28.96 7.62,29.21 | 38.73,48.9 C5.2
  Bottom 1.422: C6.- 144.78,58.42 D1.A
N$1
  Bottom 1.422: S2.2 143.51,77.47 146.05,74.93 D2.A D1.C
N$2
  Bottom 1.422: J32.PWR 149.86,80.1 D4.A 149.86,64.77 138.43,64.77 D3.C
N$3
  Bottom 1.016: C7.1 Q2.2 41.91,48.26 IC1.12
N$4
  Bottom 1.016: D2.C D4.C 149.86,58.42 C6.+ C3.1 IC3.IN C8.+ C1.1 IC2.IN
N$5
  Bottom 1.016: C9.1 Q2.1 38.1,40.64 43.18,45.72 IC1.13
N$6
  Bottom 1.016: C12.1 60.96,58.42 63.5,55.88 IC1.32
N$7
  Bottom 1.016: R2.2 LED1.K
N$8
  Bottom 1.016: IC1.9 46.99,55.88 44.45,53.34 R3.2 C5.1
N$9
  Bottom 1.016: IC1.33 64.77,58.42 63.5,59.69 63.5,78.74 R1.1
N$10
  Bottom 1.016: R1.2 71.12,91.44 67.31,95.25 41.91,95.25 36.83,90.17 16.51,90.17 LED2.K
N$11
  Bottom 1.016: 68.58,76.2 68.58,86.36 66.32,88.62 S1.2 S1.1 54.89,91.44 X1.1 | 68.58,76.2 IC1.40 | 68.58,76.2 JP1.11
N$12
  Bottom 1.016: J7.1 IC1.8
N$13
  Bottom 1.016: R12.2 LED3.K
N$14
  Bottom 1.016: J14.1 IC6.7
N$15
  Bottom 1.016: IC1.28 74.93,45.72 77.47,48.26 85.09,48.26 99.06,62.23 99.06,73.66 101.6,76.2 IC6.3
N$16
  Bottom 1.016: IC1.27 74.93,43.18 77.47,45.72 85.09,45.72 101.6,62.23 101.6,72.39 102.87,73.66 IC6.4
N$17
  Bottom 1.016: IC6.5 104.14,71.12 104.14,62.23 85.09,43.18 77.47,43.18 74.93,40.64 IC1.26
N$18
  Bottom 1.016: IC1.21 78.74,27.94 81.28,30.48 85.09,30.48 86.36,31.75 J29.1
N$19
  Bottom 1.016: J30.1 88.9,30.48 86.36,27.94 82.55,27.94 81.28,26.67 81.28,22.86 78.74,20.32 66.04,20.32 64.77,19.05 60.96,19.05 55.88,24.13 55.88,31.75 54.61,33.02 IC1.18
N$20
  Bottom 1.016: IC1.25 92.71,38.1 100.33,45.72 J27.1
N$21
  Bottom 1.016: IC1.24 J28.1
N$22
  Bottom 1.016: C14.1 48.18,8.97 R11.1A 50.64,8.89 62.23,8.89 J20.2
N$23
  Bottom 1.016: IC5.11 121.92,35.56 119.38,38.1 R5.2 114.3,38.1 114.3,54.61 IC6.11
N$24
  Bottom 1.016: IC6.12 120.65,60.96 121.92,59.69 121.92,58.42 116.84,53.34 R6.2 120.65,40.64 123.19,38.1 IC5.10
N$25
  Bottom 1.016: J14.2 111.76,50.8 111.76,35.56 R4.2 118.11,35.56 120.65,33.02 IC5.12
N$26
  Bottom 1.016: J7.2 45.72,91.44 R12.1
N$27
  Bottom 1.016: IC5.5 135.51,33.02 C16.-
N$28
  Bottom 1.016: IC5.3 135.51,27.94 C15.-
N$29
  Bottom 1.016: IC5.1 134.62,22.86 135.89,24.13 C15.+
N$30
  Bottom 1.016: IC5.4 135.51,30.48 C16.+
N$31
  Bottom 1.016: IC5.2 130.81,25.4 128.27,22.86 128.27,19.43 C17.-
N$32
  Bottom 1.016: J37.2 137.16,41.02 C18.+
N$33
  Bottom 1.016: J11.2 IC6.6
N$34
  Bottom 1.016: IC6.15 124.46,68.58 127,71.12 J8.1
N$35
  Bottom 1.016: IC6.16 123.19,71.12 124.46,72.39 J9.1
N$36
  Bottom 1.016: IC6.17 119.38,73.66 J10.1
N$37
  Bottom 1.016: IC4.1 93.98,60.96 96.52,63.5 C21.+
N$38
  Bottom 1.016: C21.- 93.09,65.66 IC4.3
N$39
  Bottom 1.016: IC4.4 96.14,68.58 C22.+
N$40
  Bottom 1.016: IC4.5 96.14,71.12 C22.-
N$41
  Bottom 1.016: IC4.2 91.44,63.5 88.9,60.96 88.9,57.53 C23.-
N$42
  Bottom 1.016: IC4.6 96.14,73.66 C24.+
N$43
  Bottom 1.016: J16.1 66.04,25.4 60.96,30.48 60.96,39.37 59.69,40.64 IC1.15
N$44
  Bottom 1.016: IC1.14 J21.1
N$45
  Bottom 1.016: J15.1 IC4.14
N$46
  Bottom 1.016: RS232.3 87.63,81.28 88.9,80.01 88.9,69.85 87.63,68.58 IC4.13
N$47
  Bottom 1.016: IC1.1 38.1,76.2 13.97,52.07 11.42,52.07 U$1.14
N$48
  Bottom 1.016: IC1.2 38.1,73.66 13.97,49.53 11.42,49.53 U$1.13
N$49
  Bottom 1.016: IC1.3 38.1,71.12 13.97,46.99 11.42,46.99 U$1.12
N$50
  Bottom 1.016: IC1.4 38.1,68.58 13.97,44.45 11.42,44.45 U$1.11
N$51
  Bottom 1.016: IC1.5 43.18,66.04 15.24,38.1 15.24,33.02 13.97,31.75 11.42,31.75 U$1.6
N$52
  Bottom 1.016: IC1.6 43.18,63.5 17.78,38.1 17.78,30.48 13.97,26.67 11.42,26.67 U$1.4
N$53
  Bottom 1.016: R7.S 21.59,10.16 17.78,13.97 17.78,21.59 15.24,24.13 11.42,24.13 U$1.3
N$54
  Bottom 1.016: R9.1 128.27,10.16 123.19,10.16 115.57,17.78 115.57,22.86 120.65,27.94 IC5.14
N$55
  Bottom 1.016: IC5.7 139.7,38.1 R10.1
N$56
  Bottom 1.016: R8.1 IC5.13
N$57
  Bottom 1.016: R10.2 140.97,12.7 143.51,10.16 TO_BOOSTER.3
N$58
  Bottom 1.016: TO_BOOSTER.2 R9.2
N$59
  Bottom 1.016: R8.2 118.11,17.78 121.92,13.97 D5.C
N$60
  Bottom 1.016: D5.A 132.72,3.81 TO_BOOSTER.1
N$61
  Bottom 1.422: J8.2 S88.3
N$62
  Bottom 1.422: J9.2 S88.4
N$63
  Bottom 1.422: J10.2 S88.5
N$64
  Bottom 1.016: J12.1 132.08,90.17 S88.1
N$65
  Bottom 1.016: J11.1 106.68,82.55 107.95,83.82 128.27,83.82 J12.2
N$66
  Bottom 1.016: RS232.5 93.12,84.68 J13.2
N$67
  Bottom 1.016: IC1.7 43.18,60.96 25.4,43.18 25.4,17.78 35.56,7.62 45.72,7.62 48.26,5.08 64.77,5.08 68.58,8.89 87.63,8.89 93.98,15.24 100.33,15.24 101.6,13.97 R15.1
N$68
  Bottom 1.016: RS232.1 82.14,88.8 | 82.14,88.8 RS232.6 | RS232.4 90.37,82.35 91.44,81.28 95.25,81.28 96.52,82.55 96.52,88.9 93.98,91.44 84.78,91.44 82.14,88.8
N$69
  Bottom 1.016: RS232.7 RS232.8
N$70
  Bottom 1.016: RS232.2 84.89,84.89 81.28,81.28 J15.2
N$71
  Bottom 1.016: IC4.11 80.01,73.66 76.2,69.85 J16.2
N$72
  Bottom 1.016: IC1.39 JP1.10
N$73
  Bottom 1.016: IC1.38 JP1.9
N$74
  Bottom 1.016: IC4.12 81.28,71.12 78.74,68.58 J17.2
N$75
  Bottom 1.016: IC1.37 JP1.8
N$76
  Bottom 1.016: J17.1 78.74,24.13 77.47,22.86 66.04,22.86 58.42,30.48 J21.2
N$77
  Bottom 1.016: IC6.13 123.19,63.5 124.46,62.23 124.46,58.42 119.38,53.34 J26.2
N$78
  Bottom 1.016: IC6.14 124.46,66.04 127,63.5 127,58.42 121.92,53.34 121.92,46.99 120.65,45.72 J27.2
N$79
  Bottom 1.016: J28.2 99.06,48.26 J26.1
N$80
  Bottom 1.016: IC6.8 107.95,63.5 86.36,41.91 J29.2
N$81
  Bottom 1.016: IC6.9 107.95,60.96 88.9,41.91 J30.2
N$82
  Bottom 1.016: IC1.22 J24.2
N$83
  Bottom 1.422: J32.GND 147.29,88.34 J32.GNDBREAK 141.7,84.55 S2.1
N$84
  Bottom 1.016: R11.S2 61.04,16.43 52.07,25.4 IC1.20
N$85
  Bottom 1.016: IC1.17 44.45,35.56 43.18,34.29 43.18,20.32 45.72,17.78 C13.1 49.21,17.78 R11.1E
N$86
  Bottom 1.016: IC1.29 64.77,48.26 63.5,46.99 J20.1
N$87
  Bottom 1.016: IC1.36 JP1.7
N$88
  Bottom 1.016: IC1.19 49.53,30.48 48.26,31.75 J34.1
N$89
  Bottom 1.016: J36.1 J41.2
N$90
  Bottom 1.016: J43.1 45.72,43.18 J34.2
N$91
  Bottom 1.016: IC1.35 JP1.6
N$92
  Bottom 1.016: IC1.34 JP1.5
N$93
  Bottom 1.016: J18.1 IC1.16
N$94
  Bottom 1.016: J18.2 45.72,29.21 60.96,13.97 68.58,13.97 71.12,16.51 J19.1
N$95
  Bottom 1.016: J19.2 J23.1
N$96
  Bottom 1.016: JP1.4 J23.2
N$97
  Bottom 1.016: IC1.23 J31.2
N$98
  Bottom 1.016: 86.36,25.4 J31.1 | 86.36,25.4 88.9,25.4 R14.1 | X2.3 86.36,25.4
N$99
  Bottom 1.016: J24.1 74.93,17.78 X2.2 78.74,16.51 R13.2
N$100
  Bottom 1.016: IC5.6 J37.1
N$101
  Bottom 1.016: Q1.2 113.67,17.14 R15.2
N$102
  Bottom 1.016: 114.3,25.4 111.76,22.86 Q1.3 | 114.3,25.4 R19.1 | 114.3,25.4 114.3,30.48 | 114.3,30.48 D6.A | K1.A2 102.81,31.81 104.14,30.48 114.3,30.48
N$103
  Bottom 1.016: J36.2 22.86,16.51 34.29,5.08 44.45,5.08 48.26,1.27 64.77,1.27 69.85,6.35 88.9,6.35 95.19,12.64 95.31,12.64 | 95.31,12.64 K1.13 | X3.2 100.33,7.62 | X3.2 100.33,5.08 | 95.31,12.64 96.58,12.64 100.33,8.89 X3.2
N$104
  Bottom 1.016: J40.2 20.32,15.24 33.02,2.54 J38.1
N$105
  Bottom 1.016: K1.14 K1.22 105.33,17.86 109.22,13.97 109.22,11.43 110.49,10.16 X3.4
N$106
  Bottom 1.016: J38.2 71.12,1.27 95.25,1.27 | 95.25,1.27 105.41,1.27 | 105.41,1.27 113.03,1.27 115.57,3.81 X3.5 | 105.41,1.27 X3.3 | 95.25,1.27 X3.1
N$108
  Bottom 1.016: 120.65,5.08 X3.6 120.65,7.62 119.38,8.89 115.57,8.89 111.76,12.7 111.76,13.97 102.87,22.86 K1.21
N$109
  Bottom 1.016: J42.2 J40.1
N$110
  Bottom 1.016: J43.2 J44.1
N$111
  Bottom 1.016: J45.1 J44.2
N$112
  Bottom 1.016: J45.2 34.29,81.28 34.29,85.09 OK1.4
N$113
  Bottom 1.016: OK1.2 C25.2 24.13,82.55 17.78,76.2 J42.1 11.43,69.85 R18.1 7.62,83.82 R16.2
N$114
  Bottom 1.016: OK1.1 30.48,87.63 R17.1
N$115
  Bottom 1.016: C25.1 22.86,87.63 R17.2 R16.1 19.05,82.55 D7.C
N$116
  Bottom 1.016: J41.1 25.4,72.39 R18.2 D7.A
N$117
  Bottom 1.016: LED4.K 107.95,26.67 R19.2
PE
  Bottom 1.016: X2.PE X2.PE@
V+  (3 unrouted)
  Bottom 1.016: IC2.OUT C2.1 J6.1 | J35.2 152.4,17.78 J6.2 | J33.2 132.08,87.63 120.65,87.63 119.38,88.9 S88.6 | J35.1 J33.1

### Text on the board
Bottom: RS232 | S88 | POWER | STOP | DCS_V1 | WWW.DIGITALPLAYGROUND.BE | EXT | CON | BST | CONTR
